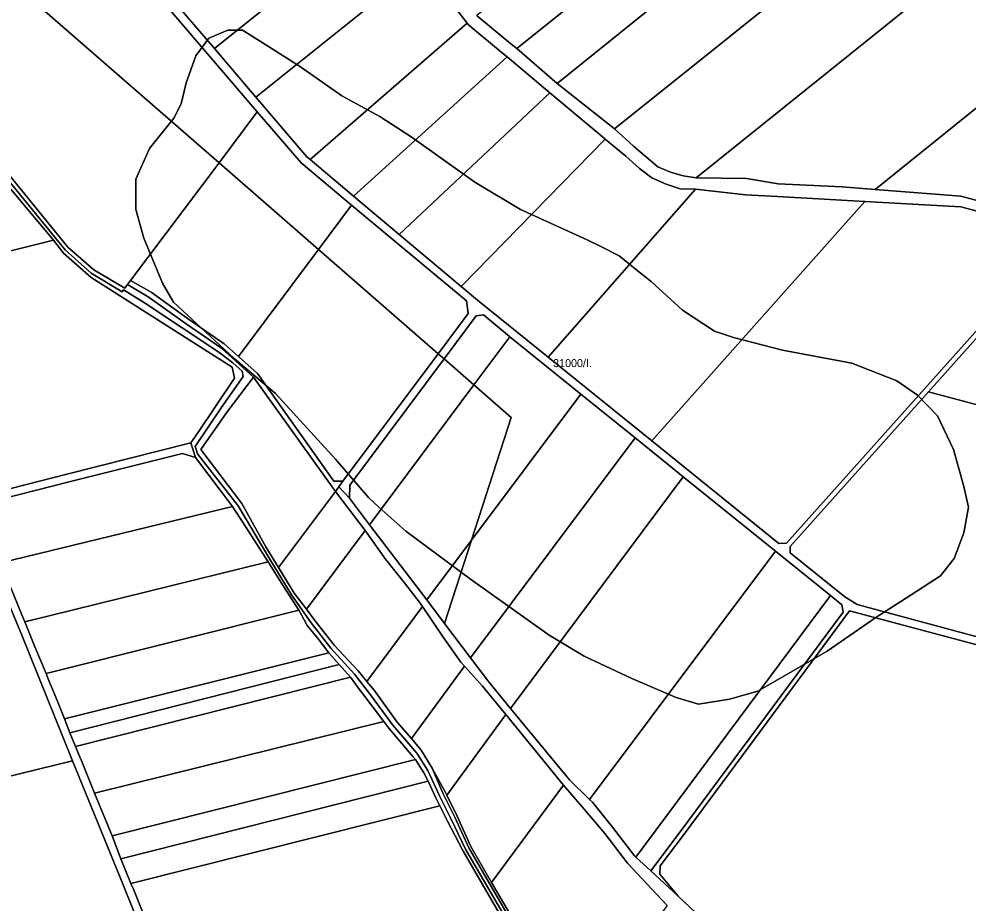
# Model space of a CAD drawing. Extents: x -541351 to -537540, y -1162694 to -1159725.
# Drawn here: x -539463 to -538870, y -1160828 to -1160275 of the extents above; entities that cross this region are included whole.
import ezdxf

# ---------------------------------------------------------------- set-up
doc = ezdxf.new("R2010")
doc.units = 0
for name, color, linetype in [('95560013', 7, 'Continuous'), ('95610013', 7, 'Continuous'), ('95630013', 7, 'Continuous'), ('95640013', 7, 'Continuous'), ('95660013', 7, 'Continuous')]:
    doc.layers.add(name, color=color, linetype=linetype)

msp = doc.modelspace()

# ---------------------------------------------------------------- linework, layer by layer
at = {"layer": '95560013'}
for points in [[(-538959.62, -1160097.82), (-538956.49, -1160100.62), (-538935.46, -1160119.47), (-539152.16, -1160293.52), (-539155.94, -1160290.64), (-539176.56, -1160273.52), (-539177.24, -1160272.53), (-539067.6, -1160184.51)], [(-538910.96, -1160141.13), (-539127.06, -1160315.25), (-539152.16, -1160293.52), (-538935.46, -1160119.47)], [(-539094.38, -1160341.15), (-539127.06, -1160315.25), (-538910.96, -1160141.13), (-538887.73, -1160161.8), (-538875.02, -1160170.41), (-539091.17, -1160343.7)], [(-539341.25, -1160293.53), (-539385.29, -1160241.92), (-539250.94, -1160160.23), (-539247.17, -1160184.44), (-539237.55, -1160210.2)], [(-538831.18, -1160196.34), (-538821.3, -1160198.29), (-539040.21, -1160374.33), (-539048.36, -1160373.06), (-539056.23, -1160370.78), (-539064.1, -1160367.35), (-539079.28, -1160354.4), (-539091.17, -1160343.7), (-538875.02, -1160170.41), (-538863.17, -1160182.34)], [(-538621.71, -1160187.61), (-538597.32, -1160185.88), (-538553.83, -1160199.69), (-538532.84, -1160213.45), (-538778.94, -1160411.23), (-538874.8, -1160385.7), (-538928.34, -1160381.56), (-538718.14, -1160212.05), (-538699.62, -1160211.88)], [(-538988.93, -1160377.95), (-539008.72, -1160374.73), (-539040.21, -1160374.33), (-538821.3, -1160198.29), (-538777.62, -1160206.88), (-538729.24, -1160212.16), (-538718.14, -1160212.05), (-538928.34, -1160381.56), (-538948.98, -1160379.96)], [(-539428.87, -1160202.88), (-539423.65, -1160205.41), (-539314.44, -1160333.03), (-539338.32, -1160364.79), (-539463.26, -1160255.92)], [(-539315.32, -1160323.92), (-539341.25, -1160293.53), (-539237.55, -1160210.2), (-539235.42, -1160215.92), (-539224.77, -1160229.29), (-539212.25, -1160241.09)], [(-539196.85, -1160259.88), (-539183.21, -1160277.53), (-539281.49, -1160362.9), (-539283.48, -1160361.23), (-539315.32, -1160323.92), (-539212.25, -1160241.09)], [(-539161.25, -1160296.33), (-539158.37, -1160298.74), (-539254.28, -1160385.71), (-539281.49, -1160362.9), (-539183.21, -1160277.53), (-539182.23, -1160278.79)], [(-539254.28, -1160385.71), (-539158.37, -1160298.74), (-539131.64, -1160321.1), (-539225.75, -1160409.65)], [(-539187.06, -1160442.11), (-539225.75, -1160409.65), (-539131.64, -1160321.1), (-539100.19, -1160347.41), (-539097, -1160350.07)], [(-539314.44, -1160333.03), (-539287.14, -1160364.93), (-539255.5, -1160391.26), (-539276.18, -1160418.95), (-539338.32, -1160364.79)], [(-539050.13, -1160381.07), (-539040.55, -1160381.4), (-539132.63, -1160486.38), (-539176.75, -1160450.77), (-539187.06, -1160442.11), (-539097, -1160350.07), (-539084.19, -1160360.78), (-539075.66, -1160368.49), (-539067.91, -1160374.21), (-539058.9, -1160378.15)], [(-539441.86, -1160413.3), (-539546.4, -1160439.25), (-539631.19, -1160460.88), (-539628.67, -1160447.82), (-539621.83, -1160426.91), (-539616.32, -1160408.3), (-539612.5, -1160397.88), (-539482.59, -1160364.66)], [(-539040.55, -1160381.4), (-539009.33, -1160384.8), (-538989.36, -1160385.91), (-538949.42, -1160388.13), (-538934.85, -1160388.95), (-539067.96, -1160538.57), (-539132.63, -1160486.38)], [(-539255.5, -1160391.26), (-539183.7, -1160451.01), (-539182.61, -1160458.98), (-539201.41, -1160484.12), (-539276.18, -1160418.95)], [(-538988.47, -1160602.73), (-539067.96, -1160538.57), (-538934.85, -1160388.95), (-538874.79, -1160392.29), (-538815.82, -1160408.08), (-538814.47, -1160413.51), (-538983.69, -1160602.58)], [(-539546.4, -1160439.25), (-539441.86, -1160413.3), (-539435.54, -1160421.37), (-539418.31, -1160436.62), (-539347.78, -1160481.25), (-539330.09, -1160492.45), (-539328.62, -1160499.34), (-539351.71, -1160533.5), (-539356, -1160539.85), (-539433.55, -1160559.47), (-539486.63, -1160572.87), (-539493.35, -1160569.31), (-539512.18, -1160522.86), (-539523.19, -1160495.68)], [(-538809.96, -1160412.69), (-538804.8, -1160411.03), (-538714.39, -1160435.25), (-538708.61, -1160437.58), (-538629.02, -1160477.47), (-538628.18, -1160482.56), (-538689.17, -1160562.99), (-538895.03, -1160507.86)], [(-539156.88, -1160473.33), (-539156.63, -1160473.53), (-539179.06, -1160503.6), (-539197.72, -1160487.34), (-539177.67, -1160460.52), (-539173.03, -1160459.89)], [(-539112.21, -1160509.38), (-539180.55, -1160600.7), (-539155.7, -1160523.96), (-539179.06, -1160503.6), (-539156.63, -1160473.53)], [(-539309.15, -1160604.74), (-539324.22, -1160577.77), (-539349.79, -1160543.92), (-539333.25, -1160520.38), (-539316.91, -1160498.74), (-539265.58, -1160570.18), (-539301.24, -1160617.66)], [(-539155.7, -1160523.96), (-539180.55, -1160600.7), (-539208.42, -1160637.94), (-539244.24, -1160591), (-539179.06, -1160503.6)], [(-539112.21, -1160509.38), (-539078.28, -1160536.77), (-539181.14, -1160674.1), (-539197.36, -1160652.6), (-539180.55, -1160600.7)], [(-538947.34, -1160635.92), (-538981.39, -1160608.44), (-538981.47, -1160604.56), (-538895.03, -1160507.86), (-538689.17, -1160562.99), (-538778.59, -1160680.91), (-538782.64, -1160683), (-538939.54, -1160640.87)], [(-539170, -1160688.87), (-539181.14, -1160674.1), (-539078.28, -1160536.77), (-539057.56, -1160553.5), (-539048.24, -1160561.01), (-539156.16, -1160705.71)], [(-539474.71, -1160614.69), (-539487.77, -1160583.34), (-539484.64, -1160577.59), (-539432.01, -1160564.25), (-539361.14, -1160546.51), (-539353.04, -1160549.08), (-539330.05, -1160579.53)], [(-539106.78, -1160762.57), (-539119.4, -1160750.45), (-539156.16, -1160705.71), (-539048.24, -1160561.01), (-538990.6, -1160607.5)], [(-539291.4, -1160633.74), (-539301.24, -1160617.66), (-539265.58, -1160570.18), (-539246.94, -1160594.62), (-539283.75, -1160643.82)], [(-539307.63, -1160614.15), (-539459.78, -1160651.69), (-539460.16, -1160650.71), (-539470.7, -1160624.83), (-539474.71, -1160614.69), (-539330.05, -1160579.53), (-539328.91, -1160581.29), (-539323.61, -1160589.17)], [(-539221.81, -1160628.07), (-539213.34, -1160639.09), (-539211.27, -1160642.16), (-539245.9, -1160688.87), (-539251.45, -1160682.3), (-539266.3, -1160666.41), (-539278.49, -1160650.74), (-539283.75, -1160643.82), (-539246.94, -1160594.62), (-539234.4, -1160612.53)], [(-539104.9, -1160764.37), (-539106.78, -1160762.57), (-538990.6, -1160607.5), (-538956.25, -1160635.2), (-539077.81, -1160798.64), (-539078.62, -1160797.89), (-539092.44, -1160780.01)], [(-539288.56, -1160644.25), (-539446.5, -1160683.86), (-539453.4, -1160667.29), (-539459.78, -1160651.69), (-539307.63, -1160614.15), (-539298.32, -1160629.08)], [(-539599.23, -1160779.87), (-539609.66, -1160743.12), (-539625.46, -1160670.68), (-539473.34, -1160631.89), (-539461.68, -1160659.92), (-539430.38, -1160737.54), (-539429.99, -1160738.47)], [(-539286.67, -1160647.66), (-539285.19, -1160650.32), (-539283.19, -1160653.91), (-539276.48, -1160662.36), (-539269.66, -1160670.94), (-539435.06, -1160712.19), (-539438.8, -1160702.92), (-539442.51, -1160693.74), (-539443.9, -1160690.3), (-539445.1, -1160687.34), (-539446.5, -1160683.86), (-539288.56, -1160644.25)], [(-539198.78, -1160660.64), (-539187.18, -1160676.86), (-539184.91, -1160679.39), (-539218.11, -1160724.6), (-539226.94, -1160714.26), (-539241.32, -1160694.3), (-539245.9, -1160688.87), (-539211.27, -1160642.16)], [(-538936.41, -1160932.83), (-538941.86, -1160929.93), (-539006.76, -1160867.53), (-539023.31, -1160851.37), (-539036.93, -1160836.79), (-539051.37, -1160823.12), (-539062.82, -1160809.24), (-539062.72, -1160804.09), (-539047.66, -1160784.3), (-538944.37, -1160644.78), (-538780.28, -1160688.55), (-538705.74, -1160708.79), (-538703.32, -1160712.7), (-538773.26, -1160973.06), (-538776.17, -1160975.29), (-538851.4, -1160955.36)], [(-539269.66, -1160670.94), (-539263.25, -1160678.25), (-539431.53, -1160720.93), (-539435.06, -1160712.19)], [(-539256.31, -1160686.17), (-539428.09, -1160729.43), (-539431.53, -1160720.93), (-539263.25, -1160678.25)], [(-539173.73, -1160691.8), (-539159.22, -1160709.51), (-539196.09, -1160759.86), (-539196.85, -1160758.33), (-539205.22, -1160742.97), (-539212.05, -1160731.79), (-539218.11, -1160724.6), (-539184.91, -1160679.39)], [(-539416.12, -1160758.67), (-539424.64, -1160737.8), (-539425.22, -1160736.52), (-539428.09, -1160729.43), (-539256.31, -1160686.17), (-539250.82, -1160693.68), (-539247.18, -1160698.2), (-539235.4, -1160713.97)], [(-539180.96, -1160792.07), (-539189.5, -1160773.11), (-539196.09, -1160759.86), (-539159.22, -1160709.51), (-539123.11, -1160753.62), (-539168.09, -1160814.49)], [(-539405.21, -1160785.38), (-539416.12, -1160758.67), (-539235.4, -1160713.97), (-539232.28, -1160718.14), (-539217.25, -1160735.75), (-539215.66, -1160737.75)], [(-539571.49, -1160879.49), (-539576.96, -1160860.94), (-539589.32, -1160816.2), (-539599.23, -1160779.87), (-539429.99, -1160738.47), (-539398.34, -1160816), (-539391.52, -1160833.04)], [(-539399.83, -1160799.65), (-539405.21, -1160785.38), (-539215.66, -1160737.75), (-539210.35, -1160745.98), (-539207.65, -1160751.23)], [(-539393.55, -1160815.07), (-539399.83, -1160799.65), (-539207.65, -1160751.23), (-539202.94, -1160761.5), (-539200.33, -1160766.57)], [(-539319, -1160999.73), (-539338.81, -1160950.75), (-539344.03, -1160937.82), (-539360.64, -1160896.43), (-539362.62, -1160891.49), (-539391.92, -1160818.73), (-539393.55, -1160815.07), (-539200.33, -1160766.57), (-539198.59, -1160770.28), (-539195.58, -1160776.25), (-539186.06, -1160794.51), (-539159.57, -1160840.01), (-539158.05, -1160842.31), (-539133.25, -1160884.16), (-539132.01, -1160885.98), (-539122.7, -1160903.87), (-539115.7, -1160931.14), (-539217.82, -1160965.59)]]:
    msp.add_lwpolyline(points, close=True, dxfattribs=at)
for points in [[(-539502.48, -1160191.42), (-539422.88, -1160197.87), (-539385.29, -1160241.92), (-539341.25, -1160293.53), (-539315.32, -1160323.92), (-539283.48, -1160361.23), (-539281.49, -1160362.9), (-539254.28, -1160385.71), (-539225.75, -1160409.65), (-539187.06, -1160442.11), (-539176.75, -1160450.77), (-539132.63, -1160486.38), (-539067.96, -1160538.57), (-538988.47, -1160602.73), (-538983.69, -1160602.58), (-538814.47, -1160413.51)], [(-538780.28, -1160688.55), (-538944.37, -1160644.78), (-539047.66, -1160784.3), (-539062.72, -1160804.09), (-539062.82, -1160809.24), (-539051.37, -1160823.12), (-539068.56, -1160807.2), (-539050.23, -1160782.75), (-538948.39, -1160645.61), (-538949.08, -1160640.98), (-538956.25, -1160635.2), (-538990.6, -1160607.5), (-539048.24, -1160561.01), (-539057.56, -1160553.5), (-539078.28, -1160536.77), (-539112.21, -1160509.38), (-539156.63, -1160473.53), (-539156.88, -1160473.33), (-539173.03, -1160459.89), (-539177.67, -1160460.52), (-539197.72, -1160487.34), (-539201.41, -1160484.12), (-539182.61, -1160458.98), (-539183.7, -1160451.01), (-539255.5, -1160391.26), (-539287.14, -1160364.93), (-539314.44, -1160333.03), (-539423.65, -1160205.41)], [(-538809.96, -1160412.69), (-538895.03, -1160507.86), (-538981.47, -1160604.56), (-538981.39, -1160608.44), (-538947.34, -1160635.92), (-538939.54, -1160640.87), (-538782.64, -1160683)], [(-539486.63, -1160572.87), (-539433.55, -1160559.47), (-539356, -1160539.85), (-539353.04, -1160549.08), (-539361.14, -1160546.51), (-539432.01, -1160564.25), (-539484.64, -1160577.59)], [(-539470.7, -1160624.83), (-539460.16, -1160650.71), (-539459.78, -1160651.69), (-539453.4, -1160667.29), (-539446.5, -1160683.86), (-539445.1, -1160687.34), (-539443.9, -1160690.3), (-539442.51, -1160693.74), (-539438.8, -1160702.92), (-539435.06, -1160712.19), (-539431.53, -1160720.93), (-539428.09, -1160729.43), (-539425.22, -1160736.52), (-539424.64, -1160737.8), (-539416.12, -1160758.67), (-539405.21, -1160785.38), (-539399.83, -1160799.65), (-539393.55, -1160815.07), (-539391.92, -1160818.73), (-539362.62, -1160891.49)], [(-539391.52, -1160833.04), (-539398.34, -1160816), (-539429.99, -1160738.47), (-539430.38, -1160737.54), (-539461.68, -1160659.92), (-539473.34, -1160631.89)]]:
    msp.add_lwpolyline(points, dxfattribs=at)
at = {"layer": '95610013'}
for points in [[(-539338.32, -1160364.79), (-539393.71, -1160438.45), (-539395.56, -1160440.92), (-539397.21, -1160443.12), (-539416.61, -1160431.81), (-539432.78, -1160417.52), (-539479.17, -1160360.89), (-539508.32, -1160325.42), (-539463.53, -1160256.34), (-539463.26, -1160255.92)], [(-539276.18, -1160418.95), (-539326.21, -1160485.94), (-539335.13, -1160477.91), (-539357.37, -1160462.6), (-539380.81, -1160445.69), (-539393.71, -1160438.45), (-539338.32, -1160364.79)], [(-539201.41, -1160484.12), (-539260.98, -1160563.77), (-539266.71, -1160563.77), (-539314.37, -1160496.6), (-539326.21, -1160485.94), (-539276.18, -1160418.95)], [(-539260.98, -1160563.77), (-539201.41, -1160484.12), (-539197.72, -1160487.34), (-539256.7, -1160566.22), (-539256.88, -1160574.42), (-539263.49, -1160567.26)], [(-539197.72, -1160487.34), (-539179.06, -1160503.6), (-539244.24, -1160591), (-539256.88, -1160574.42), (-539256.7, -1160566.22)], [(-539180.55, -1160600.7), (-539197.36, -1160652.6), (-539208.42, -1160637.94)], [(-538949.08, -1160640.98), (-538948.39, -1160645.61), (-539050.23, -1160782.75), (-539068.56, -1160807.2), (-539077.81, -1160798.64), (-538956.25, -1160635.2)], [(-539083, -1160802.43), (-539058.38, -1160828.79), (-539115.26, -1160904.98), (-539126.83, -1160883.61), (-539153.38, -1160839.71), (-539168.09, -1160814.49), (-539123.11, -1160753.62), (-539110.17, -1160768.73), (-539097.29, -1160783.9)]]:
    msp.add_lwpolyline(points, close=True, dxfattribs=at)
at = {"layer": '95630013'}
msp.add_lwpolyline([(-539113.65, -1160907.77), (-539113.58, -1160911.28), (-539128.35, -1160884.12), (-539154.76, -1160840.33), (-539182.33, -1160792.82), (-539190.9, -1160773.73), (-539198.32, -1160759.07), (-539205.22, -1160742.97), (-539196.85, -1160758.33), (-539196.09, -1160759.86), (-539189.5, -1160773.11), (-539180.96, -1160792.07), (-539168.09, -1160814.49), (-539153.38, -1160839.71), (-539126.83, -1160883.61), (-539115.26, -1160904.98)], close=True, dxfattribs=at)
at = {"layer": '95640013'}
for points in [[(-538815.82, -1160408.08), (-538874.79, -1160392.29), (-538934.85, -1160388.95), (-538949.42, -1160388.13), (-538989.36, -1160385.91), (-539009.33, -1160384.8), (-539040.55, -1160381.4), (-539050.13, -1160381.07), (-539058.9, -1160378.15), (-539067.91, -1160374.21), (-539075.66, -1160368.49), (-539084.19, -1160360.78), (-539097, -1160350.07), (-539100.19, -1160347.41), (-539131.64, -1160321.1), (-539158.37, -1160298.74), (-539161.25, -1160296.33), (-539182.23, -1160278.79), (-539183.21, -1160277.53), (-539196.85, -1160259.88)], [(-539176.56, -1160273.52), (-539155.94, -1160290.64), (-539152.16, -1160293.52), (-539127.06, -1160315.25), (-539094.38, -1160341.15), (-539091.17, -1160343.7), (-539079.28, -1160354.4), (-539064.1, -1160367.35), (-539056.23, -1160370.78), (-539048.36, -1160373.06), (-539040.21, -1160374.33), (-539008.72, -1160374.73), (-538988.93, -1160377.95), (-538948.98, -1160379.96), (-538928.34, -1160381.56), (-538874.8, -1160385.7), (-538778.94, -1160411.23)], [(-539479.17, -1160360.89), (-539432.78, -1160417.52), (-539416.61, -1160431.81), (-539397.21, -1160443.12), (-539395.56, -1160440.92), (-539382.7, -1160448.54), (-539359.5, -1160465.04), (-539336.91, -1160480.59), (-539316.91, -1160498.74), (-539333.25, -1160520.38), (-539349.79, -1160543.92), (-539324.22, -1160577.77), (-539309.15, -1160604.74), (-539301.24, -1160617.66), (-539291.4, -1160633.74), (-539283.75, -1160643.82), (-539278.49, -1160650.74), (-539266.3, -1160666.41), (-539251.45, -1160682.3), (-539245.9, -1160688.87), (-539241.32, -1160694.3), (-539226.94, -1160714.26), (-539218.11, -1160724.6), (-539212.05, -1160731.79), (-539205.22, -1160742.97), (-539198.32, -1160759.07), (-539190.9, -1160773.73), (-539182.33, -1160792.82), (-539154.76, -1160840.33)], [(-539159.57, -1160840.01), (-539186.06, -1160794.51), (-539195.58, -1160776.25), (-539198.59, -1160770.28), (-539200.33, -1160766.57), (-539202.94, -1160761.5), (-539207.65, -1160751.23), (-539210.35, -1160745.98), (-539215.66, -1160737.75), (-539217.25, -1160735.75), (-539232.28, -1160718.14), (-539235.4, -1160713.97), (-539247.18, -1160698.2), (-539250.82, -1160693.68), (-539256.31, -1160686.17), (-539263.25, -1160678.25), (-539269.66, -1160670.94), (-539276.48, -1160662.36), (-539283.19, -1160653.91), (-539285.19, -1160650.32), (-539286.67, -1160647.66), (-539288.56, -1160644.25), (-539298.32, -1160629.08), (-539307.63, -1160614.15), (-539323.61, -1160589.17), (-539328.91, -1160581.29), (-539330.05, -1160579.53), (-539353.04, -1160549.08), (-539356, -1160539.85), (-539351.71, -1160533.5), (-539328.62, -1160499.34), (-539330.09, -1160492.45), (-539347.78, -1160481.25), (-539418.31, -1160436.62), (-539435.54, -1160421.37), (-539441.86, -1160413.3), (-539482.59, -1160364.66)], [(-539481.11, -1160362.43), (-539434.58, -1160419.19), (-539418.19, -1160433.73), (-539398.91, -1160445.38), (-539398.08, -1160444.28), (-539385.02, -1160452.25), (-539361.38, -1160468.05), (-539338.49, -1160483.1), (-539329.79, -1160489.73), (-539324.02, -1160494.97), (-539323.36, -1160498.47), (-539337.05, -1160517.97), (-539353.23, -1160542.17), (-539352.67, -1160544), (-539351.86, -1160546.64), (-539326.49, -1160579.11), (-539306.68, -1160612.55), (-539292.98, -1160634.73), (-539280.84, -1160652.33), (-539268.51, -1160668.09), (-539253.79, -1160684.35), (-539244.34, -1160696.41), (-539229.75, -1160716.24), (-539214.71, -1160733.6), (-539207.89, -1160744.55), (-539200.63, -1160760.29), (-539193.24, -1160774.91), (-539184.32, -1160793.64), (-539157.26, -1160840.13)], [(-539157.26, -1160840.13), (-539184.32, -1160793.64), (-539193.24, -1160774.91), (-539200.63, -1160760.29), (-539207.89, -1160744.55), (-539214.71, -1160733.6), (-539229.75, -1160716.24), (-539244.34, -1160696.41), (-539253.79, -1160684.35), (-539268.51, -1160668.09), (-539280.84, -1160652.33), (-539292.98, -1160634.73), (-539306.68, -1160612.55), (-539326.49, -1160579.11), (-539351.86, -1160546.64), (-539352.67, -1160544), (-539353.23, -1160542.17), (-539337.05, -1160517.97), (-539323.36, -1160498.47), (-539324.02, -1160494.97), (-539329.79, -1160489.73), (-539338.49, -1160483.1), (-539361.38, -1160468.05), (-539385.02, -1160452.25), (-539398.08, -1160444.28), (-539398.91, -1160445.38), (-539418.19, -1160433.73), (-539434.58, -1160419.19), (-539481.11, -1160362.43)], [(-539058.38, -1160828.79), (-539083, -1160802.43), (-539097.29, -1160783.9), (-539110.17, -1160768.73), (-539123.11, -1160753.62), (-539159.22, -1160709.51), (-539173.73, -1160691.8), (-539184.91, -1160679.39), (-539187.18, -1160676.86), (-539198.78, -1160660.64), (-539211.27, -1160642.16), (-539213.34, -1160639.09), (-539221.81, -1160628.07), (-539234.4, -1160612.53), (-539246.94, -1160594.62), (-539265.58, -1160570.18), (-539263.49, -1160567.26), (-539256.88, -1160574.42), (-539244.24, -1160591), (-539208.42, -1160637.94), (-539197.36, -1160652.6), (-539181.14, -1160674.1), (-539170, -1160688.87), (-539156.16, -1160705.71), (-539119.4, -1160750.45), (-539106.78, -1160762.57), (-539104.9, -1160764.37), (-539092.44, -1160780.01), (-539078.62, -1160797.89), (-539077.81, -1160798.64), (-539068.56, -1160807.2), (-539051.37, -1160823.12), (-539036.93, -1160836.79)]]:
    msp.add_lwpolyline(points, dxfattribs=at)
msp.add_lwpolyline([(-539265.58, -1160570.18), (-539316.91, -1160498.74), (-539336.91, -1160480.59), (-539359.5, -1160465.04), (-539382.7, -1160448.54), (-539395.56, -1160440.92), (-539393.71, -1160438.45), (-539380.81, -1160445.69), (-539357.37, -1160462.6), (-539335.13, -1160477.91), (-539326.21, -1160485.94), (-539314.37, -1160496.6), (-539266.71, -1160563.77), (-539260.98, -1160563.77), (-539263.49, -1160567.26)], close=True, dxfattribs=at)
at = {"layer": '95660013'}
for points in [[(-539019.37, -1160700), (-539038.69, -1160703), (-539052.69, -1160699), (-539080.31, -1160687), (-539110.12, -1160673), (-539132.12, -1160660), (-539181.12, -1160625), (-539221.62, -1160595), (-539238.5, -1160580), (-539245, -1160574), (-539265.62, -1160550), (-539303.12, -1160509), (-539329.12, -1160487), (-539366.87, -1160452), (-539373.81, -1160440), (-539385.37, -1160412), (-539390.37, -1160394), (-539390.37, -1160375), (-539381.81, -1160356), (-539366.69, -1160337), (-539362, -1160328), (-539359, -1160315), (-539352.87, -1160298), (-539344.81, -1160287), (-539332.81, -1160282), (-539323.69, -1160282), (-539307.55, -1160292.22), (-539287.37, -1160305), (-539261.62, -1160323), (-539237.87, -1160336), (-539226.66, -1160343.22), (-539217.69, -1160349), (-539178.5, -1160377), (-539149.87, -1160394), (-539126.71, -1160404.56), (-539108.19, -1160413), (-539099.38, -1160417.44), (-539088.37, -1160423), (-539077.16, -1160431.89), (-539068.19, -1160439), (-539048.81, -1160457), (-539028.62, -1160470), (-539016.81, -1160474), (-538986.31, -1160482), (-538942.81, -1160490), (-538914.81, -1160501), (-538901.87, -1160510), (-538889.37, -1160523), (-538879.31, -1160544), (-538872.87, -1160567), (-538869.87, -1160580), (-538872.87, -1160596), (-538878.87, -1160612), (-538887.5, -1160623), (-538909.31, -1160637), (-538927.81, -1160649), (-538958.31, -1160670), (-539001.69, -1160695)], [(-539052.69, -1160699), (-539038.69, -1160703), (-539019.37, -1160700), (-539001.69, -1160695), (-538958.31, -1160670), (-538927.81, -1160649), (-538909.31, -1160637), (-538887.5, -1160623), (-538878.87, -1160612), (-538872.87, -1160596), (-538869.87, -1160580), (-538872.87, -1160567), (-538879.31, -1160544), (-538889.37, -1160523), (-538901.87, -1160510), (-538914.81, -1160501), (-538942.81, -1160490), (-538986.31, -1160482), (-539016.81, -1160474), (-539028.62, -1160470), (-539048.81, -1160457), (-539068.19, -1160439), (-539077.16, -1160431.89), (-539088.37, -1160423), (-539099.38, -1160417.44), (-539108.19, -1160413), (-539126.71, -1160404.56), (-539149.87, -1160394), (-539178.5, -1160377), (-539217.69, -1160349), (-539226.66, -1160343.22), (-539237.87, -1160336), (-539261.62, -1160323), (-539287.37, -1160305), (-539307.55, -1160292.22), (-539323.69, -1160282), (-539332.81, -1160282), (-539344.81, -1160287), (-539352.87, -1160298), (-539359, -1160315), (-539362, -1160328), (-539366.69, -1160337), (-539381.81, -1160356), (-539390.37, -1160375), (-539390.37, -1160394), (-539385.37, -1160412), (-539373.81, -1160440), (-539366.87, -1160452), (-539329.12, -1160487), (-539303.12, -1160509), (-539265.62, -1160550), (-539245, -1160574), (-539238.5, -1160580), (-539221.62, -1160595), (-539181.12, -1160625), (-539132.12, -1160660), (-539110.12, -1160673), (-539080.31, -1160687)]]:
    msp.add_lwpolyline(points, close=True, dxfattribs=at)

# ---------------------------------------------------------------- texts
msp.add_text('31000/I.', height=5, rotation=0, dxfattribs=at).set_placement((-539129.53, -1160492.5))

doc.saveas('drawing.dxf')
